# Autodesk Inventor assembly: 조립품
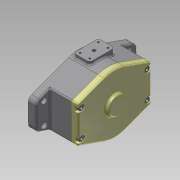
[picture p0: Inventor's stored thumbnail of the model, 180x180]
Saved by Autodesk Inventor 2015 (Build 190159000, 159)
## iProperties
Created: 2023-11
Part Number: 조립품
Document SubType Name: Assembly
Designer: user
Author: user
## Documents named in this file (14)
- C:\Users\user\Desktop\731106V1013\조립품.iam
- C:\Users\user\Desktop\731106V1013\DU 부시.ipt
- C:\Users\user\Desktop\731106V1013\O링 G90.ipt
- C:\Users\user\Desktop\731106V1013\내접기어.ipt
- C:\Users\user\Desktop\731106V1013\본체.ipt
- C:\Users\user\Desktop\731106V1013\스퍼기어.ipt
- C:\Users\user\Desktop\731106V1013\오일 실 14 25 4.ipt
- C:\Users\user\Desktop\731106V1013\오일레스 부시.ipt
- C:\Users\user\Desktop\731106V1013\육각 소켓 머리 볼트 M4 x 30.ipt
- C:\Users\user\Desktop\731106V1013\육각 소켓 머리 볼트 M6 x 12.ipt
- C:\Users\user\Desktop\731106V1013\축.ipt
- C:\Users\user\Desktop\731106V1013\커버.ipt
- C:\Users\user\Desktop\731106V1013\크레센트.ipt
- C:\Users\user\Desktop\731106V1013\평행 키 5x5x22.ipt
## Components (2 placed, 2 different names)
1. DU 부시:1
2. O링 G90:1
